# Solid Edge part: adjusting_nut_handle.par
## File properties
Title: Adjusting nut handle
Author: vicky Raina
Template: Normal.par
Last saved by: Cadcim
Revision: 7
Application: Solid Edge
Density: 0 kg/mm^3
Accuracy: 0.99
Material: aluminum
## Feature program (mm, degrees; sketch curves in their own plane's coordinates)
sketch for "unnamed Protrusion 1" plane through (0, 0, 0) normal (0, -1, 0) x-axis (1, 0, 0)
  circle centre (0, 0) radius 9.5123
extrude "unnamed Protrusion 1" add finite 127 symmetric
chamfer "Chamfer_1" setback 1.5748
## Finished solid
Body 1: solid body, 5 faces, 4 edges, 0 vertices.
  Faces by surface: cone 2, plane 2, cylinder 1
  Edges by curve: circle 4
Bounding box of the edges (mm): 19.025 x 127.000 x 19.025, from (-9.5123, -63.5, -9.5123) to (9.5123, 63.5, 9.5123).
Cylindrical faces by radius (mm): R9.5123 x1
Conical faces (half-angle, radius in mm at the cone's reference point): 45 deg R7.9375 x1, 45 deg R9.5123 x1
Planar faces by outward normal: +y 1, -y 1
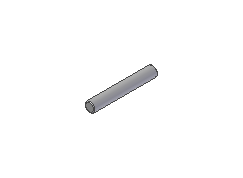
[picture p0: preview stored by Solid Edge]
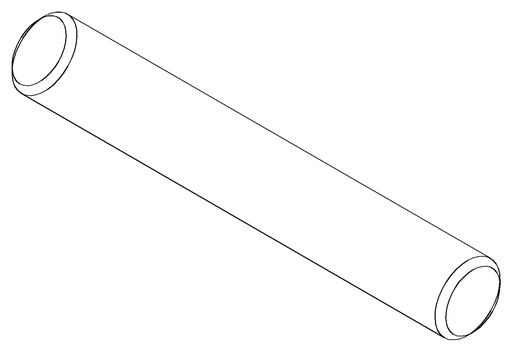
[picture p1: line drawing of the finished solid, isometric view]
